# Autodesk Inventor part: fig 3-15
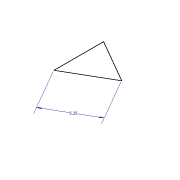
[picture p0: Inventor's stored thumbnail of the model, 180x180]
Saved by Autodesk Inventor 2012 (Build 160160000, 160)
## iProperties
Created: 2009-11
Part Number: fig 3-15
Document SubType Name: Modeling
Designer: Sham
Density: 1 g/cm^3
Material: Default
Author: Sham
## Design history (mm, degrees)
sketch "Sketch1"
  geometry: L1 (0.077, -0.115)-(0.077, -5.365); L2 (0.077, -5.365)-(4.624, -2.74); L3 (4.624, -2.74)-(0.077, -0.115)
  constraints: 6 end point, 2 equal length, 1 vertical
  dimensions: "d1" = 5.25 dimension on L1.start L1.end L1 L2.end L2 L3; "d1" = 5.25 distance of L1.end L2.end
